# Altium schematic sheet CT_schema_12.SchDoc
size 387 x 278 mm
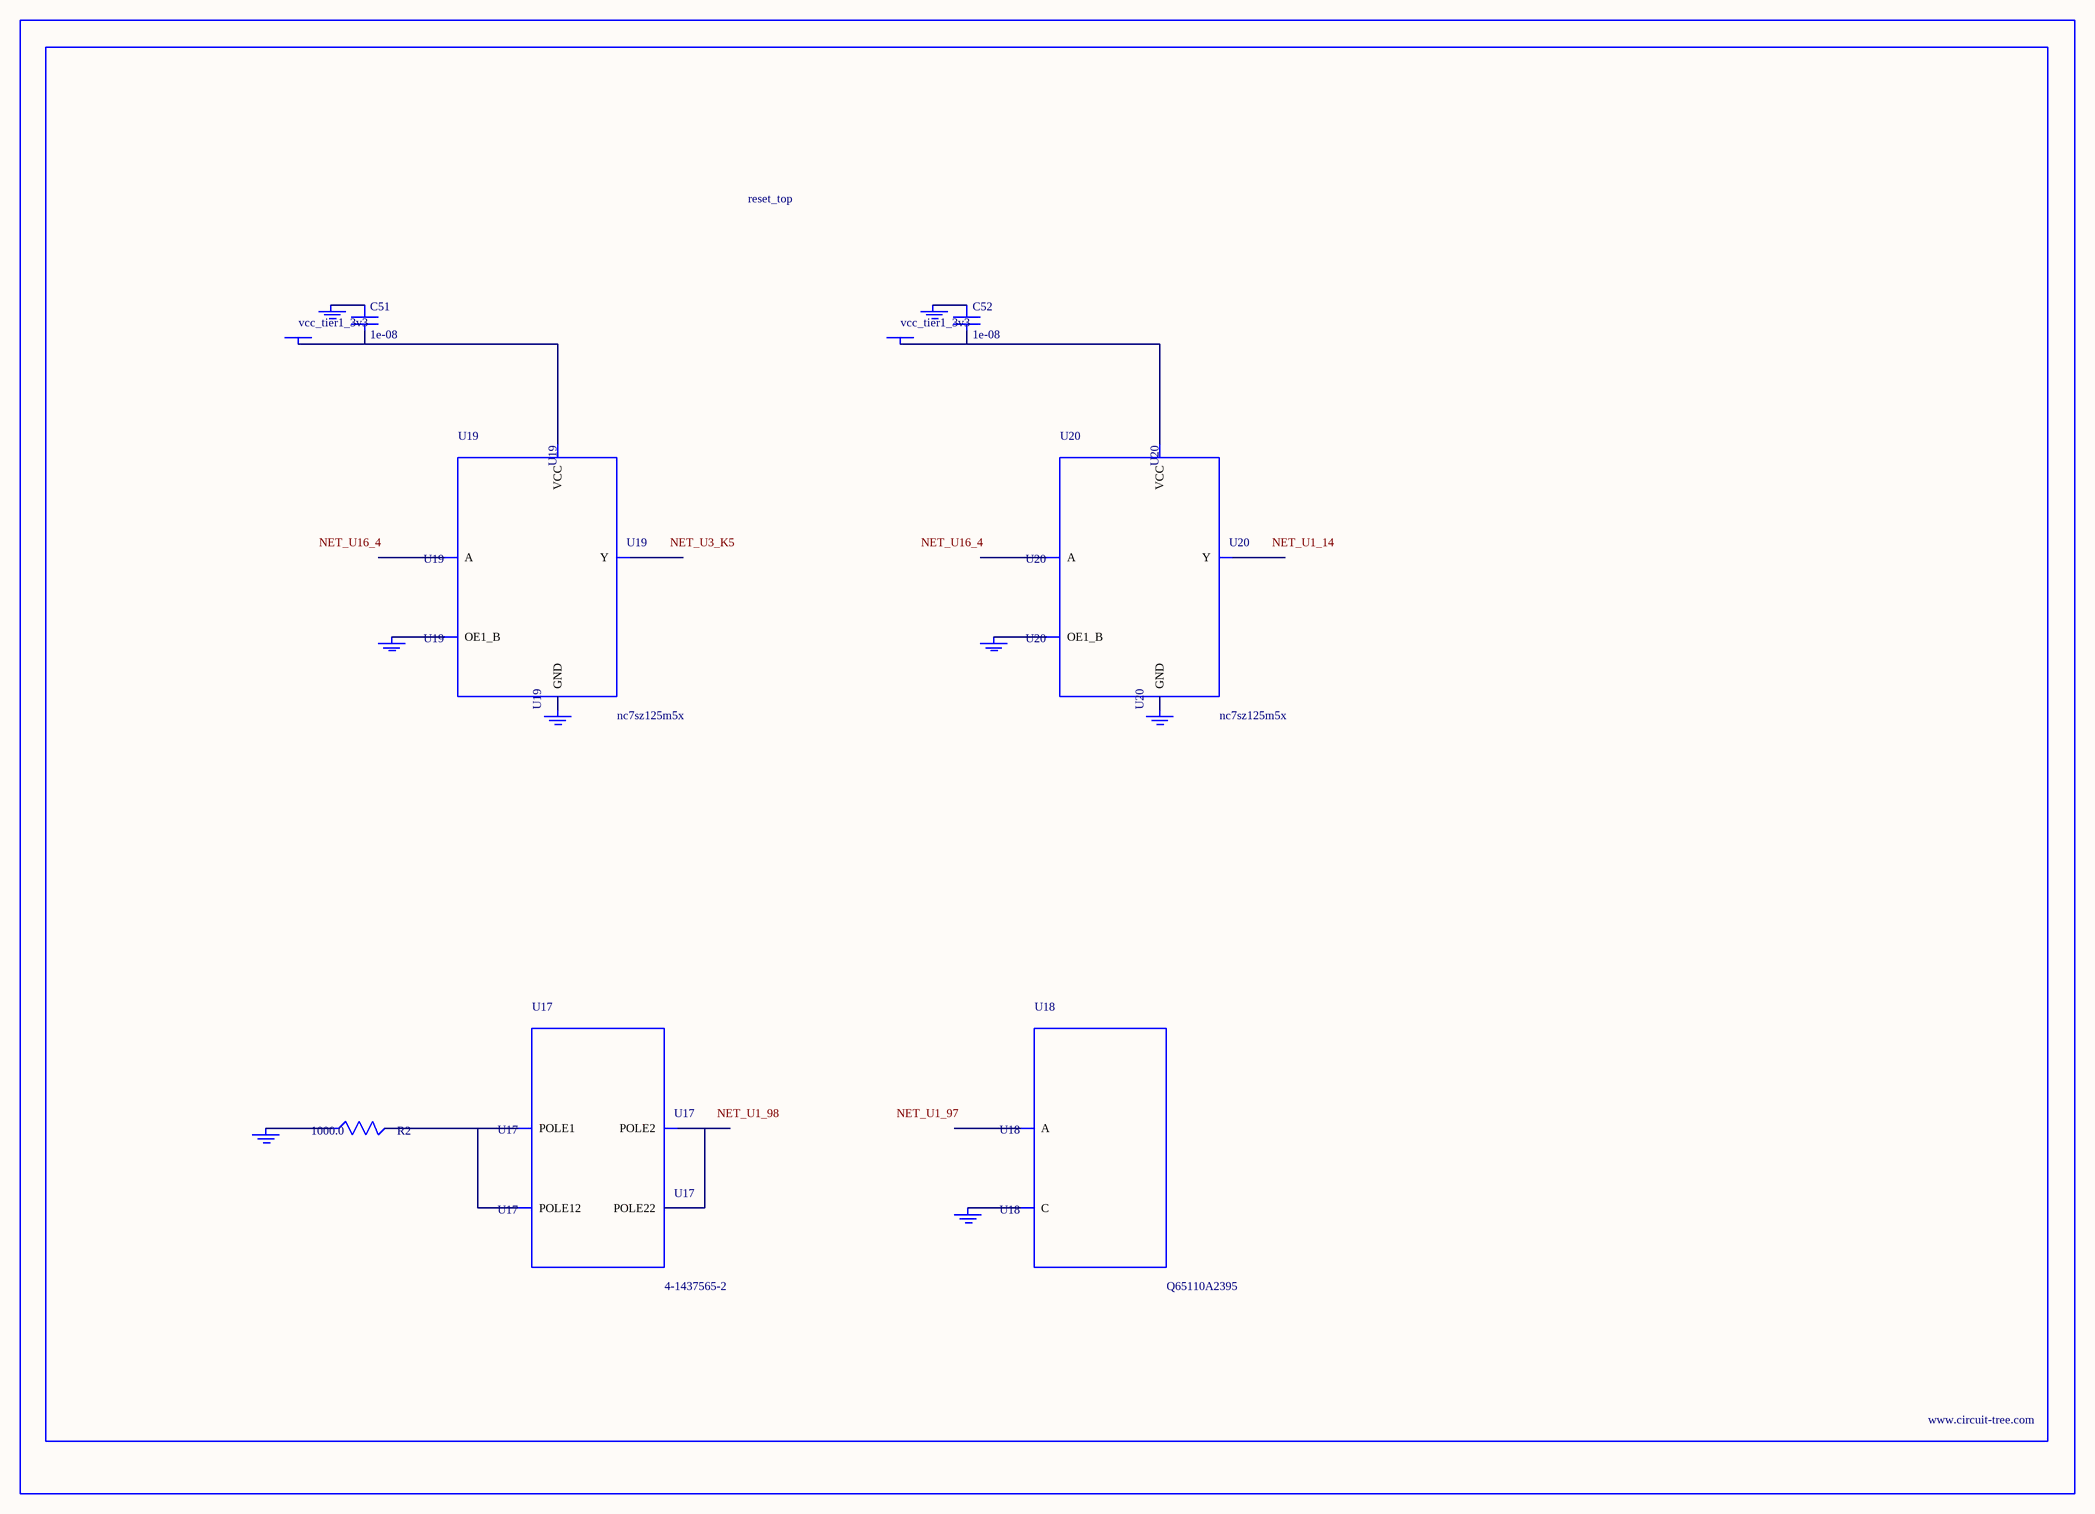
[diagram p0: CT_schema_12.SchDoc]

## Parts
BORDER11  (no value)
C51  1e-08  [C0402]
C52  1e-08  [C0402]
GND_INSTANCE_11_0  (no value)
GND_INSTANCE_11_1  (no value)
GND_INSTANCE_11_2  (no value)
GND_INSTANCE_11_3  (no value)
GND_INSTANCE_11_4  (no value)
GND_INSTANCE_11_5  (no value)
GND_INSTANCE_11_6  (no value)
GND_INSTANCE_11_7  (no value)
POWER_INSTANCE_11_0  vcc_tier1_3v3
POWER_INSTANCE_11_1  vcc_tier1_3v3
R2  1000.0  [R0603]
U17  4-1437565-2  [SW_4-1437565-2]
U18  Q65110A2395  [LGM67K-G1J2-24-Z]
U19  nc7sz125m5x  [NC7SZ125M5X]
U20  nc7sz125m5x  [NC7SZ125M5X]

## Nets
NetC51_1: C51.1 GND_INSTANCE_11_2.0(GND)
NetC51_2: C51.2 POWER_INSTANCE_11_0.0(PWR) U19.5(VCC)
NetC52_1: C52.1 GND_INSTANCE_11_5.0(GND)
NetC52_2: C52.2 POWER_INSTANCE_11_1.0(PWR) U20.5(VCC)
NetGND_INSTANCE_11_0_0: GND_INSTANCE_11_0.0(GND) R2.1
NetGND_INSTANCE_11_1_0: GND_INSTANCE_11_1.0(GND) U18.C
NetGND_INSTANCE_11_3_0: GND_INSTANCE_11_3.0(GND) U19.1(OE1_B)
NetGND_INSTANCE_11_4_0: GND_INSTANCE_11_4.0(GND) U19.3(GND)
NetGND_INSTANCE_11_6_0: GND_INSTANCE_11_6.0(GND) U20.1(OE1_B)
NetGND_INSTANCE_11_7_0: GND_INSTANCE_11_7.0(GND) U20.3(GND)
NetR2_2: R2.2 U17.1(POLE1) U17.2(POLE12)
NetU17_3: U17.3(POLE2) U17.4(POLE22)

Not connected (* = marked no-connect by the designer): U18 A; U19 2(A) 4(Y); U20 2(A) 4(Y)

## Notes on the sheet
- Labels drawn without touching a wire or pin: NET_U1_14, NET_U1_97, NET_U1_98, NET_U3_K5, NET_U16_4

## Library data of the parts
BORDER11 = BORDER_PAGE11
C51 C52 = C0402C103K3RAC
GND_INSTANCE_11_0-GND_INSTANCE_11_7 = GND
POWER_INSTANCE_11_0 POWER_INSTANCE_11_1 = PWR
R2 = RC0603JR-071KL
